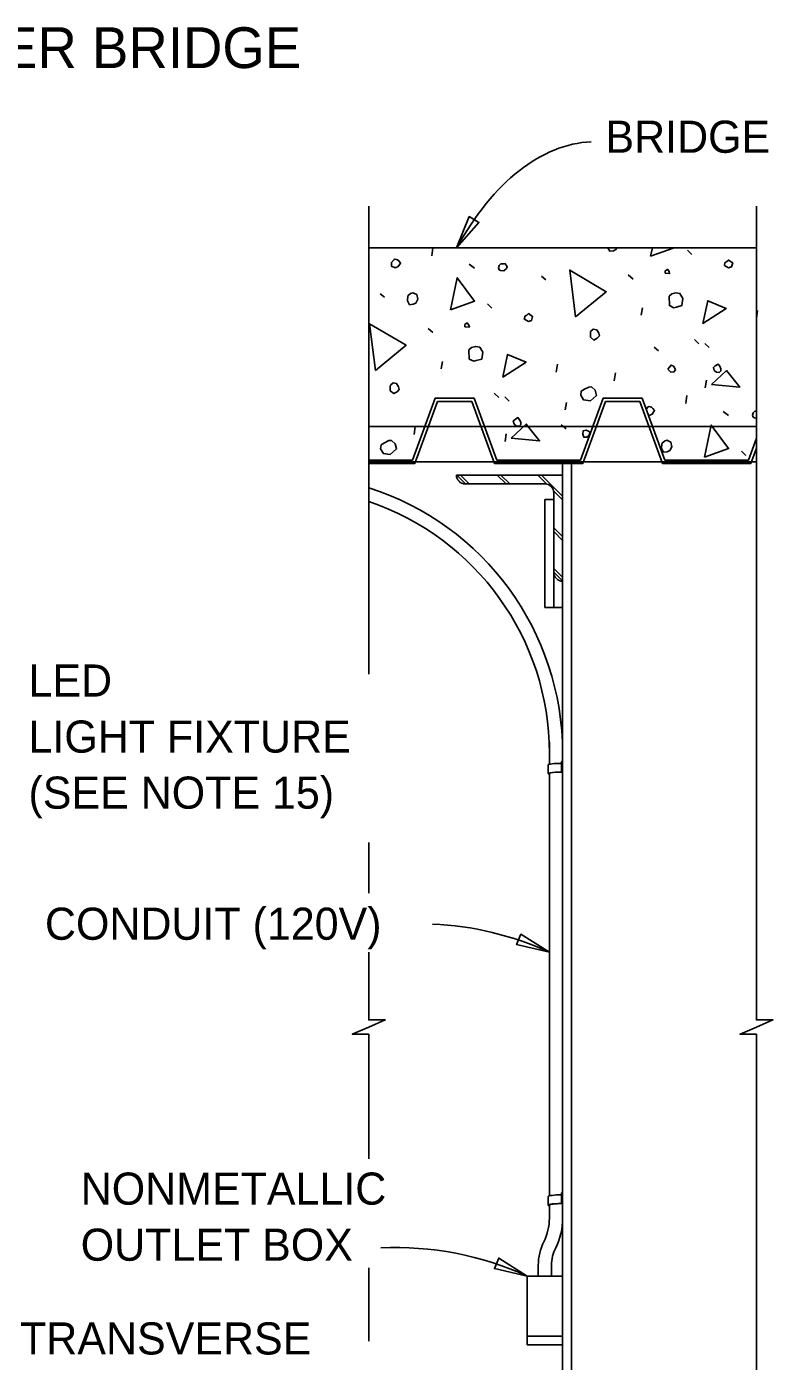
# Model space of a CAD drawing. Extents: x -1660015.2 to -1659984.9, y 2580594.2 to 2580616.7.
# Drawn here: x -1660006.46 to -1660002.94, y 2580598.81 to 2580605.1 of the extents above; entities that cross this region are included whole.
import ezdxf

# ---------------------------------------------------------------- set-up
doc = ezdxf.new("R2010")
doc.units = 0
for name, color, linetype in [('Default', 7, 'Continuous'), ('Miscellaneous', 7, 'Continuous'), ('Miscellaneous3', 7, 'Continuous'), ('PlotBorder_dp', 7, 'Continuous'), ('SheetLines_dp', 7, 'Continuous'), ('SteelGirder', 7, 'Continuous')]:
    doc.layers.add(name, color=color, linetype=linetype)

msp = doc.modelspace()

# ---------------------------------------------------------------- linework, layer by layer
at = {"layer": 'Default'}
for p, q in [((-1660004.8501, 2580603.2146), (-1660004.5689, 2580603.2146)), ((-1660004.322, 2580603.2146), (-1660003.7785, 2580603.2146)), ((-1660003.5316, 2580603.2146), (-1660003.0252, 2580603.2146)), ((-1660004.8501, 2580603.0479), (-1660004.6296, 2580603.0479)), ((-1660004.2613, 2580603.0479), (-1660003.8392, 2580603.0479)), ((-1660003.4709, 2580603.0479), (-1660003.0487, 2580603.0479)), ((-1660003.9999, 2580601.7278), (-1660003.9999, 2580601.6232)), ((-1660003.9999, 2580601.5796), (-1660003.9999, 2580599.5911)), ((-1660003.9999, 2580599.5474), (-1660003.9999, 2580599.4857)), ((-1660004.052, 2580599.2131), (-1660004.052, 2580599.2635)), ((-1660003.9895, 2580599.2131), (-1660003.9895, 2580599.2635)), ((-1660003.9374, 2580599.2131), (-1660004.1041, 2580599.2131)), ((-1660004.1041, 2580599.2131), (-1660004.1041, 2580598.8898)), ((-1660003.9374, 2580598.9302), (-1660004.1041, 2580598.9302)), ((-1660003.9374, 2580598.8898), (-1660004.1041, 2580598.8898))]:
    msp.add_line(p, q, dxfattribs=at)
for centre, radius, start, end in [((-1660005.2499, 2580601.6757), 1.3125, 0.00119, 72.26682), ((-1660005.2499, 2580601.6757), 1.25, 0, 71.34833), ((-1660004.2499, 2580599.4857), 0.25, 333.61151, 0), ((-1660004.2499, 2580599.4857), 0.3125, 333.61151, 0.00004), ((-1660003.802, 2580599.2635), 0.25, 153.61151, 179.99999), ((-1660003.802, 2580599.2635), 0.1875, 153.61151, 179.99999)]:
    msp.add_arc(centre, radius, start, end, dxfattribs=at)
at = {"layer": 'Miscellaneous'}
for p, q in [((-1660004.5538, 2580604.0168), (-1660004.5484, 2580604.0545)), ((-1660003.3499, 2580604.0443), (-1660003.3289, 2580604.0241)), ((-1660004.3779, 2580603.9785), (-1660004.3521, 2580603.9596)), ((-1660004.0367, 2580603.9224), (-1660004.0164, 2580603.9046)), ((-1660003.6293, 2580603.9281), (-1660003.6059, 2580603.9084)), ((-1660004.7958, 2580603.8381), (-1660004.7761, 2580603.8226)), ((-1660004.2917, 2580603.792), (-1660004.2707, 2580603.7717)), ((-1660003.5679, 2580603.7375), (-1660003.5618, 2580603.7727)), ((-1660003.0255, 2580603.7223), (-1660003.0201, 2580603.76)), ((-1660004.5711, 2580603.6757), (-1660004.5477, 2580603.6561)), ((-1660003.5072, 2580603.5881), (-1660003.4868, 2580603.5702)), ((-1660003.3173, 2580603.6234), (-1660003.2964, 2580603.6032)), ((-1660003.2685, 2580603.6054), (-1660003.2476, 2580603.5852)), ((-1660004.5097, 2580603.4851), (-1660004.5036, 2580603.5204)), ((-1660003.9673, 2580603.47), (-1660003.9618, 2580603.5077)), ((-1660003.6949, 2580603.4291), (-1660003.6895, 2580603.4668)), ((-1660003.2668, 2580603.3963), (-1660003.2607, 2580603.4315)), ((-1660004.6433, 2580603.0559), (-1660004.5371, 2580603.3477)), ((-1660004.3538, 2580603.3477), (-1660004.5371, 2580603.3477)), ((-1660004.2476, 2580603.0559), (-1660004.3538, 2580603.3477)), ((-1660004.2591, 2580603.3711), (-1660004.2382, 2580603.3508)), ((-1660004.2103, 2580603.3531), (-1660004.1893, 2580603.3328)), ((-1660003.8529, 2580603.0559), (-1660003.7467, 2580603.3477)), ((-1660003.5634, 2580603.3477), (-1660003.7467, 2580603.3477)), ((-1660003.4572, 2580603.0559), (-1660003.5634, 2580603.3477)), ((-1660003.3584, 2580603.3225), (-1660003.3529, 2580603.3602)), ((-1660004.6324, 2580603.0403), (-1660004.5262, 2580603.3321)), ((-1660004.3647, 2580603.3321), (-1660004.5262, 2580603.3321)), ((-1660004.2585, 2580603.0403), (-1660004.3647, 2580603.3321)), ((-1660003.9249, 2580603.2924), (-1660003.9188, 2580603.3277)), ((-1660003.8419, 2580603.0403), (-1660003.7358, 2580603.3321)), ((-1660003.5743, 2580603.3321), (-1660003.7358, 2580603.3321)), ((-1660003.4681, 2580603.0403), (-1660003.5743, 2580603.3321)), ((-1660003.1825, 2580603.2843), (-1660003.1567, 2580603.2653)), ((-1660004.6367, 2580603.1767), (-1660004.6312, 2580603.2144)), ((-1660003.9449, 2580603.2223), (-1660003.9215, 2580603.2027)), ((-1660004.2086, 2580603.1439), (-1660004.2025, 2580603.1792)), ((-1660003.0624, 2580603.0559), (-1660003.0252, 2580603.1582)), ((-1660003.0962, 2580603.0977), (-1660003.0753, 2580603.0775)), ((-1660003.0515, 2580603.0403), (-1660003.0252, 2580603.1125)), ((-1660004.6433, 2580603.0559), (-1660004.8501, 2580603.0559)), ((-1660004.6324, 2580603.0403), (-1660004.8501, 2580603.0403)), ((-1660003.8419, 2580603.0403), (-1660004.2585, 2580603.0403)), ((-1660003.8529, 2580603.0559), (-1660004.2476, 2580603.0559)), ((-1660003.0515, 2580603.0403), (-1660003.4681, 2580603.0403)), ((-1660003.0624, 2580603.0559), (-1660003.4572, 2580603.0559)), ((-1660004.3945, 2580602.9437), (-1660004.4362, 2580602.9854)), ((-1660004.3768, 2580602.9437), (-1660004.4185, 2580602.9854)), ((-1660004.2036, 2580602.9437), (-1660004.2453, 2580602.9854)), ((-1660004.1859, 2580602.9437), (-1660004.2276, 2580602.9854)), ((-1660004.0103, 2580602.9413), (-1660004.0544, 2580602.9854)), ((-1660003.9374, 2580602.8861), (-1660004.0367, 2580602.9854)), ((-1660003.9374, 2580602.8684), (-1660003.9817, 2580602.9128)), ((-1660003.9374, 2580602.6952), (-1660003.9791, 2580602.7369)), ((-1660003.9374, 2580602.6775), (-1660003.9791, 2580602.7192)), ((-1660003.9374, 2580602.5043), (-1660003.9791, 2580602.5459)), ((-1660003.9374, 2580602.4866), (-1660003.9791, 2580602.5283))]:
    msp.add_line(p, q, dxfattribs=at)
for points in [[(-1660003.7253, 2580604.056), (-1660003.7161, 2580604.0394), (-1660003.6985, 2580604.0415), (-1660003.6871, 2580604.0472), (-1660003.682, 2580604.056)], [(-1660003.5235, 2580604.0159), (-1660003.515, 2580604.056)], [(-1660003.4121, 2580604.056), (-1660003.5235, 2580604.0159)], [(-1660004.7425, 2580603.9869), (-1660004.7428, 2580603.9688), (-1660004.7251, 2580603.9606), (-1660004.7112, 2580603.9669), (-1660004.7, 2580603.9828), (-1660004.708, 2580603.9936), (-1660004.7148, 2580603.9995), (-1660004.7258, 2580604.0018), (-1660004.7306, 2580604.0005), (-1660004.7425, 2580603.9869)], [(-1660004.2361, 2580603.9518), (-1660004.23, 2580603.9483), (-1660004.2142, 2580603.9473), (-1660004.2017, 2580603.9584), (-1660004.1988, 2580603.967), (-1660004.2075, 2580603.9802), (-1660004.2281, 2580603.9798), (-1660004.2365, 2580603.9724), (-1660004.2387, 2580603.9615), (-1660004.2361, 2580603.9518)], [(-1660003.1752, 2580603.9721), (-1660003.1569, 2580603.9615), (-1660003.1424, 2580603.9654), (-1660003.1372, 2580603.9848), (-1660003.1563, 2580603.9979), (-1660003.1646, 2580603.9904), (-1660003.1736, 2580603.9854), (-1660003.1752, 2580603.9721), (-1660003.1765, 2580603.9769)], [(-1660004.4652, 2580603.7636), (-1660004.4332, 2580603.9145), (-1660004.3519, 2580603.8043), (-1660004.4652, 2580603.7636)], [(-1660003.8764, 2580603.7298), (-1660003.9044, 2580603.9501), (-1660003.7323, 2580603.8487), (-1660003.8764, 2580603.7298)], [(-1660003.4554, 2580603.9358), (-1660003.4341, 2580603.9338), (-1660003.4367, 2580603.9434), (-1660003.4448, 2580603.9542), (-1660003.4556, 2580603.9461), (-1660003.4554, 2580603.9358)], [(-1660004.6664, 2580603.8287), (-1660004.6679, 2580603.8051), (-1660004.6579, 2580603.787), (-1660004.6403, 2580603.7892), (-1660004.6289, 2580603.7948), (-1660004.6183, 2580603.8132), (-1660004.6241, 2580603.8349), (-1660004.6418, 2580603.8431), (-1660004.6539, 2580603.8399), (-1660004.6664, 2580603.8287)], [(-1660003.4366, 2580603.827), (-1660003.4352, 2580603.7833), (-1660003.4145, 2580603.7734), (-1660003.4024, 2580603.7766), (-1660003.3758, 2580603.7837), (-1660003.3715, 2580603.816), (-1660003.3859, 2580603.8406), (-1660003.4047, 2580603.8433), (-1660003.424, 2580603.8381), (-1660003.4366, 2580603.827)], [(-1660003.278, 2580603.6987), (-1660003.2549, 2580603.8058), (-1660003.1676, 2580603.7697), (-1660003.278, 2580603.6987)], [(-1660004.117, 2580603.7197), (-1660004.0986, 2580603.7091), (-1660004.0841, 2580603.713), (-1660004.079, 2580603.7325), (-1660004.098, 2580603.7455), (-1660004.1064, 2580603.7381), (-1660004.1154, 2580603.7331), (-1660004.117, 2580603.7197), (-1660004.1183, 2580603.7246)], [(-1660004.8182, 2580603.4775), (-1660004.8462, 2580603.6978), (-1660004.6741, 2580603.5963), (-1660004.8182, 2580603.4775)], [(-1660004.3972, 2580603.6835), (-1660004.3759, 2580603.6814), (-1660004.3785, 2580603.6911), (-1660004.3866, 2580603.7019), (-1660004.3973, 2580603.6938), (-1660004.3972, 2580603.6835)], [(-1660003.8066, 2580603.6528), (-1660003.8069, 2580603.6346), (-1660003.7903, 2580603.6209), (-1660003.7747, 2580603.6303), (-1660003.7646, 2580603.6408), (-1660003.7678, 2580603.6528), (-1660003.7772, 2580603.6684), (-1660003.7936, 2580603.6718), (-1660003.8061, 2580603.6607), (-1660003.8066, 2580603.6528)], [(-1660004.3784, 2580603.5746), (-1660004.377, 2580603.531), (-1660004.3562, 2580603.521), (-1660004.3442, 2580603.5243), (-1660004.3176, 2580603.5314), (-1660004.3133, 2580603.5636), (-1660004.3277, 2580603.5882), (-1660004.3465, 2580603.5909), (-1660004.3658, 2580603.5858), (-1660004.3784, 2580603.5746)], [(-1660004.2197, 2580603.4463), (-1660004.1967, 2580603.5534), (-1660004.1094, 2580603.5173), (-1660004.2197, 2580603.4463)], [(-1660003.4429, 2580603.4836), (-1660003.4288, 2580603.4693), (-1660003.4136, 2580603.4708), (-1660003.4059, 2580603.4806), (-1660003.4072, 2580603.4855), (-1660003.4159, 2580603.4987), (-1660003.4275, 2580603.5033), (-1660003.4352, 2580603.4935), (-1660003.4429, 2580603.4836)], [(-1660003.2374, 2580603.4119), (-1660003.1669, 2580603.4774), (-1660003.1043, 2580603.3984), (-1660003.2374, 2580603.4119)], [(-1660003.2239, 2580603.4776), (-1660003.2141, 2580603.4699), (-1660003.2007, 2580603.4683), (-1660003.1924, 2580603.4757), (-1660003.1925, 2580603.486), (-1660003.1982, 2580603.4975), (-1660003.2062, 2580603.5082), (-1660003.2194, 2580603.4995), (-1660003.2278, 2580603.4921), (-1660003.2239, 2580603.4776)], [(-1660004.7484, 2580603.4004), (-1660004.7487, 2580603.3822), (-1660004.7321, 2580603.3686), (-1660004.7165, 2580603.3779), (-1660004.7063, 2580603.3884), (-1660004.7096, 2580603.4005), (-1660004.7189, 2580603.4161), (-1660004.7354, 2580603.4195), (-1660004.7479, 2580603.4083), (-1660004.7484, 2580603.4004)], [(-1660003.8526, 2580603.3609), (-1660003.8389, 2580603.3387), (-1660003.8067, 2580603.3344), (-1660003.7774, 2580603.3604), (-1660003.7839, 2580603.3845), (-1660003.8012, 2580603.4006), (-1660003.8139, 2580603.3998), (-1660003.8343, 2580603.3891), (-1660003.8499, 2580603.3798), (-1660003.8526, 2580603.3609)], [(-1660003.5346, 2580603.2686), (-1660003.5296, 2580603.2663), (-1660003.5158, 2580603.2726), (-1660003.5045, 2580603.2886), (-1660003.5126, 2580603.2993), (-1660003.5194, 2580603.3053), (-1660003.5303, 2580603.3075), (-1660003.5352, 2580603.3062), (-1660003.5445, 2580603.2957)], [(-1660003.0252, 2580603.2857), (-1660003.0327, 2580603.2856), (-1660003.0411, 2580603.2782), (-1660003.0433, 2580603.2672), (-1660003.0407, 2580603.2575)], [(-1660004.1791, 2580603.1596), (-1660004.1087, 2580603.225), (-1660004.0461, 2580603.146), (-1660004.1791, 2580603.1596)], [(-1660004.1657, 2580603.2253), (-1660004.1559, 2580603.2176), (-1660004.1425, 2580603.216), (-1660004.1341, 2580603.2234), (-1660004.1343, 2580603.2337), (-1660004.14, 2580603.2451), (-1660004.148, 2580603.2559), (-1660004.1612, 2580603.2472), (-1660004.1696, 2580603.2398), (-1660004.1657, 2580603.2253)], [(-1660003.2698, 2580603.0693), (-1660003.2378, 2580603.2203), (-1660003.1565, 2580603.1101), (-1660003.2698, 2580603.0693)], [(-1660003.0407, 2580603.2575), (-1660003.0346, 2580603.254), (-1660003.0252, 2580603.2534)], [(-1660004.7944, 2580603.1086), (-1660004.7807, 2580603.0864), (-1660004.7485, 2580603.0821), (-1660004.7192, 2580603.108), (-1660004.7257, 2580603.1322), (-1660004.7429, 2580603.1483), (-1660004.7557, 2580603.1474), (-1660004.7761, 2580603.1368), (-1660004.7917, 2580603.1274), (-1660004.7944, 2580603.1086)], [(-1660003.8423, 2580603.1774), (-1660003.8384, 2580603.1629), (-1660003.8257, 2580603.1637), (-1660003.8142, 2580603.1693), (-1660003.8085, 2580603.1864), (-1660003.8152, 2580603.1924), (-1660003.8268, 2580603.197), (-1660003.8413, 2580603.1931), (-1660003.8423, 2580603.1774)], [(-1660003.471, 2580603.1345), (-1660003.4724, 2580603.1108), (-1660003.4624, 2580603.0928), (-1660003.4449, 2580603.0949), (-1660003.4335, 2580603.1005), (-1660003.4229, 2580603.1189), (-1660003.4287, 2580603.1406), (-1660003.4464, 2580603.1488), (-1660003.4585, 2580603.1456), (-1660003.471, 2580603.1345)]]:
    msp.add_lwpolyline(points, dxfattribs=at)
at = {"layer": 'Miscellaneous3'}
msp.add_line((-1660004.8501, 2580604.056), (-1660003.0252, 2580604.056), dxfattribs=at)
at = {"layer": 'SheetLines_dp'}
for points in [[(-1660004.8501, 2580602.0472), (-1660004.8501, 2580604.252)], [(-1660003.0252, 2580596.5919), (-1660003.0252, 2580600.3516), (-1660003.1027, 2580600.3516), (-1660003.0252, 2580600.3853), (-1660002.9477, 2580600.4191), (-1660003.0252, 2580600.4191), (-1660003.0252, 2580604.252)], [(-1660004.8501, 2580601.0165), (-1660004.8501, 2580601.2549)], [(-1660004.8501, 2580599.7646), (-1660004.8501, 2580600.3516), (-1660004.9276, 2580600.3516), (-1660004.8501, 2580600.3853), (-1660004.7726, 2580600.4191), (-1660004.8501, 2580600.4191), (-1660004.8501, 2580600.7384)], [(-1660004.8501, 2580598.9059), (-1660004.8501, 2580599.2521)]]:
    msp.add_lwpolyline(points, dxfattribs=at)
for points in [[(-1660004.4365, 2580604.0559), (-1660004.3318, 2580604.1748), (-1660004.3768, 2580604.2026)], [(-1660003.9999, 2580600.7384), (-1660004.1339, 2580600.8229), (-1660004.1543, 2580600.774)], [(-1660004.1041, 2580599.2131), (-1660004.2381, 2580599.2976), (-1660004.2585, 2580599.2488)]]:
    msp.add_lwpolyline(points, close=True, dxfattribs=at)
for centre, end in [((-1660004.6187, 2580599.3802), 87.36586), ((-1660004.7229, 2580597.8549), 92.69977)]:
    msp.add_arc(centre, 1.4925, 65.50737, end, dxfattribs=at)
msp.add_ellipse((-1660003.6914, 2580602.1871), major_axis=(0.1111, -2.3674), ratio=0.464296, start_param=3.141604, end_param=3.781059, dxfattribs=at)
at = {"layer": 'SteelGirder'}
for p, q in [((-1660004.322, 2580603.2146), (-1660004.5689, 2580603.2146)), ((-1660003.5316, 2580603.2146), (-1660003.7785, 2580603.2146)), ((-1660004.2613, 2580603.0479), (-1660004.6296, 2580603.0479)), ((-1660003.9374, 2580603.0403), (-1660003.9374, 2580596.798)), ((-1660003.8957, 2580603.0403), (-1660003.8957, 2580596.798)), ((-1660003.4709, 2580603.0479), (-1660003.8392, 2580603.0479)), ((-1660003.0252, 2580603.0479), (-1660003.0487, 2580603.0479)), ((-1660004.4374, 2580602.9854), (-1660003.9374, 2580602.9854)), ((-1660003.9374, 2580602.9854), (-1660003.9374, 2580602.4854)), ((-1660004.0207, 2580602.9437), (-1660004.3957, 2580602.9437)), ((-1660003.9791, 2580602.527), (-1660003.9791, 2580602.902)), ((-1660004.0208, 2580602.8708), (-1660004.0208, 2580602.361)), ((-1660004.0208, 2580602.8708), (-1660003.9791, 2580602.8708)), ((-1660003.9791, 2580602.527), (-1660003.9791, 2580602.361)), ((-1660004.0208, 2580602.361), (-1660003.9373, 2580602.361)), ((-1660003.9426, 2580601.6365), (-1660003.9374, 2580601.6365)), ((-1660003.9426, 2580601.6365), (-1660003.9426, 2580601.5871)), ((-1660004.0051, 2580601.6202), (-1660004.0051, 2580601.5796)), ((-1660003.9426, 2580601.5959), (-1660003.9374, 2580601.5959)), ((-1660004.0051, 2580599.5881), (-1660004.0051, 2580599.5475)), ((-1660003.9426, 2580599.6044), (-1660003.9374, 2580599.6044)), ((-1660003.9426, 2580599.6044), (-1660003.9426, 2580599.5549)), ((-1660003.9426, 2580599.5637), (-1660003.9374, 2580599.5637))]:
    msp.add_line(p, q, dxfattribs=at)
for centre, start, end in [((-1660004.3957, 2580602.9854), 180, 270), ((-1660004.0207, 2580602.902), 0, 90), ((-1660003.9374, 2580602.527), 180, 270)]:
    msp.add_arc(centre, 0.0417, start, end, dxfattribs=at)
for centre, ratio, start_param, end_param in [((-1660003.9426, 2580601.5796), 0.119608, 1.570506, 3.552397), ((-1660003.9426, 2580601.6202), 0.119608, 1.570506, 3.140799), ((-1660003.9374, 2580601.5796), 0.111403, 1.571206, 3.141305), ((-1660003.9426, 2580599.5881), 0.119608, 1.570506, 3.140799), ((-1660003.9426, 2580599.5474), 0.119608, 1.570506, 3.552397), ((-1660003.9374, 2580599.5474), 0.111403, 1.571206, 3.141305)]:
    msp.add_ellipse(centre, major_axis=(0.0625, 0), ratio=ratio, start_param=start_param, end_param=end_param, dxfattribs=at)

# ---------------------------------------------------------------- texts
at = {"layer": 'PlotBorder_dp'}
for s, height, p in [('LIGHTING DETAILS FOR CONCRETE BOX GIRDER BRIDGE', 0.192, (-1660012.3863, 2580604.9018)), ('BRIDGE DECK', 0.1512, (-1660003.736, 2580604.5029)), ('CONDUIT (120V)', 0.1512, (-1660006.3738, 2580600.7969))]:
    msp.add_text(s, height=height, dxfattribs=at).set_placement(p)
at = {"layer": 'SheetLines_dp'}
for s, p in [('LED', (-1660006.4512, 2580601.9421)), ('LIGHT FIXTURE', (-1660006.4512, 2580601.6781)), ('(SEE NOTE 15)', (-1660006.4512, 2580601.4141)), ('NONMETALLIC', (-1660006.2054, 2580599.5494)), ('OUTLET BOX', (-1660006.2054, 2580599.2854)), ('TRANSVERSE', (-1660006.4909, 2580598.8439))]:
    msp.add_text(s, height=0.1512, dxfattribs=at).set_placement(p)

doc.saveas('drawing.dxf')
